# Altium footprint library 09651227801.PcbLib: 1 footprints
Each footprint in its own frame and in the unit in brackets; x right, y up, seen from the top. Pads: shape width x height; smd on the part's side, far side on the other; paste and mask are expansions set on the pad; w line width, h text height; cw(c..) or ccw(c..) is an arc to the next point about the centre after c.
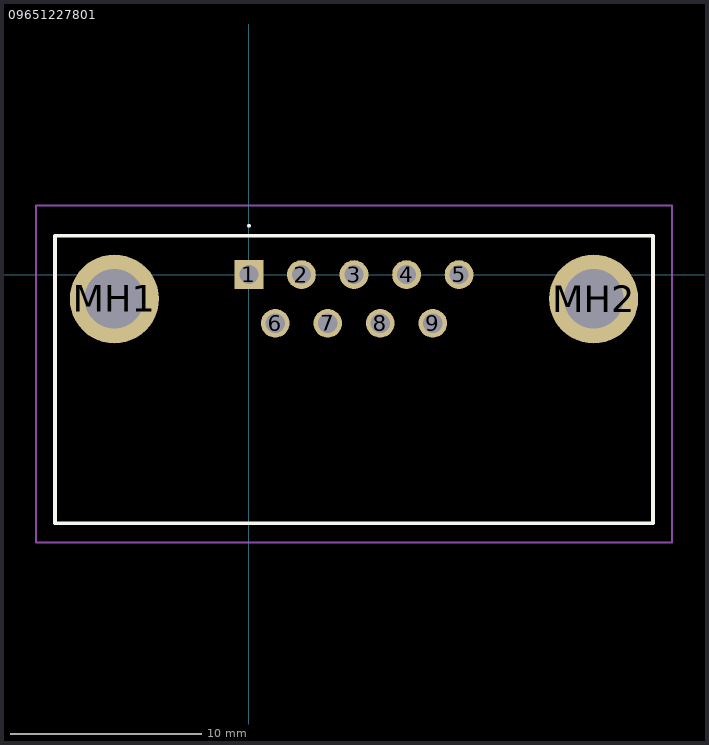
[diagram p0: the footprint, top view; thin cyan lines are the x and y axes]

## 09651227801 [mm]
pads (11):
  rect 1.5x1.5 hole 1: 1(0,0)
  round 1.5 hole 1: 2(2.74,0) 3(5.48,0) 4(8.22,0) 5(10.96,0) 6(1.37,-2.54) 7(4.11,-2.54) 8(6.85,-2.54) 9(9.59,-2.54)
  round 4.65 hole 3.1: MH1(-7.02,-1.27) MH2(17.98,-1.27)
Top Overlay:
  lines w0.1: 0,2.5 0,2.5 ; 0,2.5 ccw(c0,2.55) 0,2.6 ; 0,2.5 cw(c0,2.55) 0,2.6 ; 0,2.6 0,2.6
  lines w0.2: -10.12,-12.97 21.08,-12.97 21.08,2.03 -10.12,2.03 -10.12,-12.97
Mechanical 15:
  lines w0.1: -10.12,-12.97 21.08,-12.97 21.08,2.03 -10.12,2.03 -10.12,-12.97
Mechanical 20:
  lines w0.1: -11.12,-13.97 22.08,-13.97 22.08,3.6 -11.12,3.6 -11.12,-13.97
